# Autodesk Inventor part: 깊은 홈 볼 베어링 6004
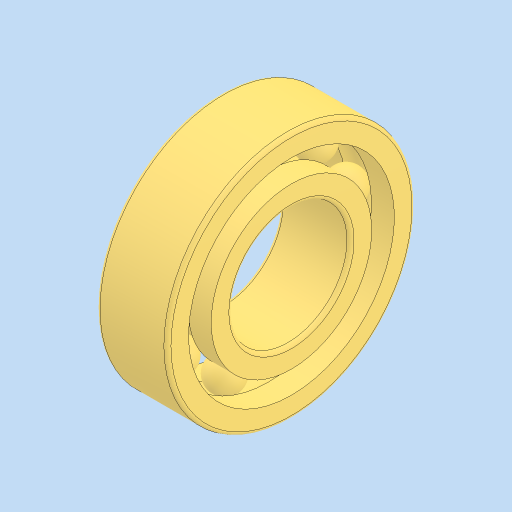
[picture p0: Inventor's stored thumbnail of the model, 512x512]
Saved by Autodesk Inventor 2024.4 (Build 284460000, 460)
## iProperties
Created: 2026-07
Part Number: 깊은 홈 볼 베어링 6004
Material: 강철, 연강
Description: 깊은 그루브 볼 베어링
Document SubType Name: Modeling
Designer: home
Density: 7.85 g/cm^3
Appearance: 기본값
Author: jhkim
Sending System: Autodesk Inventor 2027
Preprocessor: ST-DEVELOPER v20.1
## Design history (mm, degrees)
feature "Solid1"
feature "Solid1:1"
feature "Solid1:2"
feature "Solid1:3"
feature "Solid1:4"
feature "Solid1:5"
feature "Solid1:6"
feature "Solid1:7"
feature "Solid1:8"
feature "Solid1:9"
feature "Solid1:10"
node "솔리드1"
node "솔리드2"
node "솔리드3"
node "솔리드4"
node "솔리드5"
node "솔리드6"
node "솔리드7"
node "솔리드8"
node "솔리드9"
node "솔리드10"
node "솔리드11"
